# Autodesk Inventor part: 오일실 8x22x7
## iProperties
IsCustomPart: 1
Created: 2009-02
Part Number: 오일실 8x22x7
Material: 고무
Description: 오일-실
Document SubType Name: Modeling
Standard: KS B 2804
Designer: 한국산업디자인학원
Standards Organization: KS
Language: ko-KR
Size Designation: D - 8 22 7
Categories: <MemberInstance><Categories><Category DisplayName="샤프트 부품" InternalName="7f7aeb1f-a693-4053-b835-cee3144e0d98" Mnemonic="SHFT"><Category DisplayName="실링" Intern
Density: 0.93 g/cm^3
Author: 한국산업디자인학원
